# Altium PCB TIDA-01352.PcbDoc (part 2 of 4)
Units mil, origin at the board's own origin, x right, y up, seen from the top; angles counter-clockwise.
Board outline 6496.06 x 8661.42 mil, 4 copper layers (Top Layer, GND, PWR, Bottom Layer), stack 79.834 mil thick; 456 components, 240 nets, 1197 pads, 446 vias.
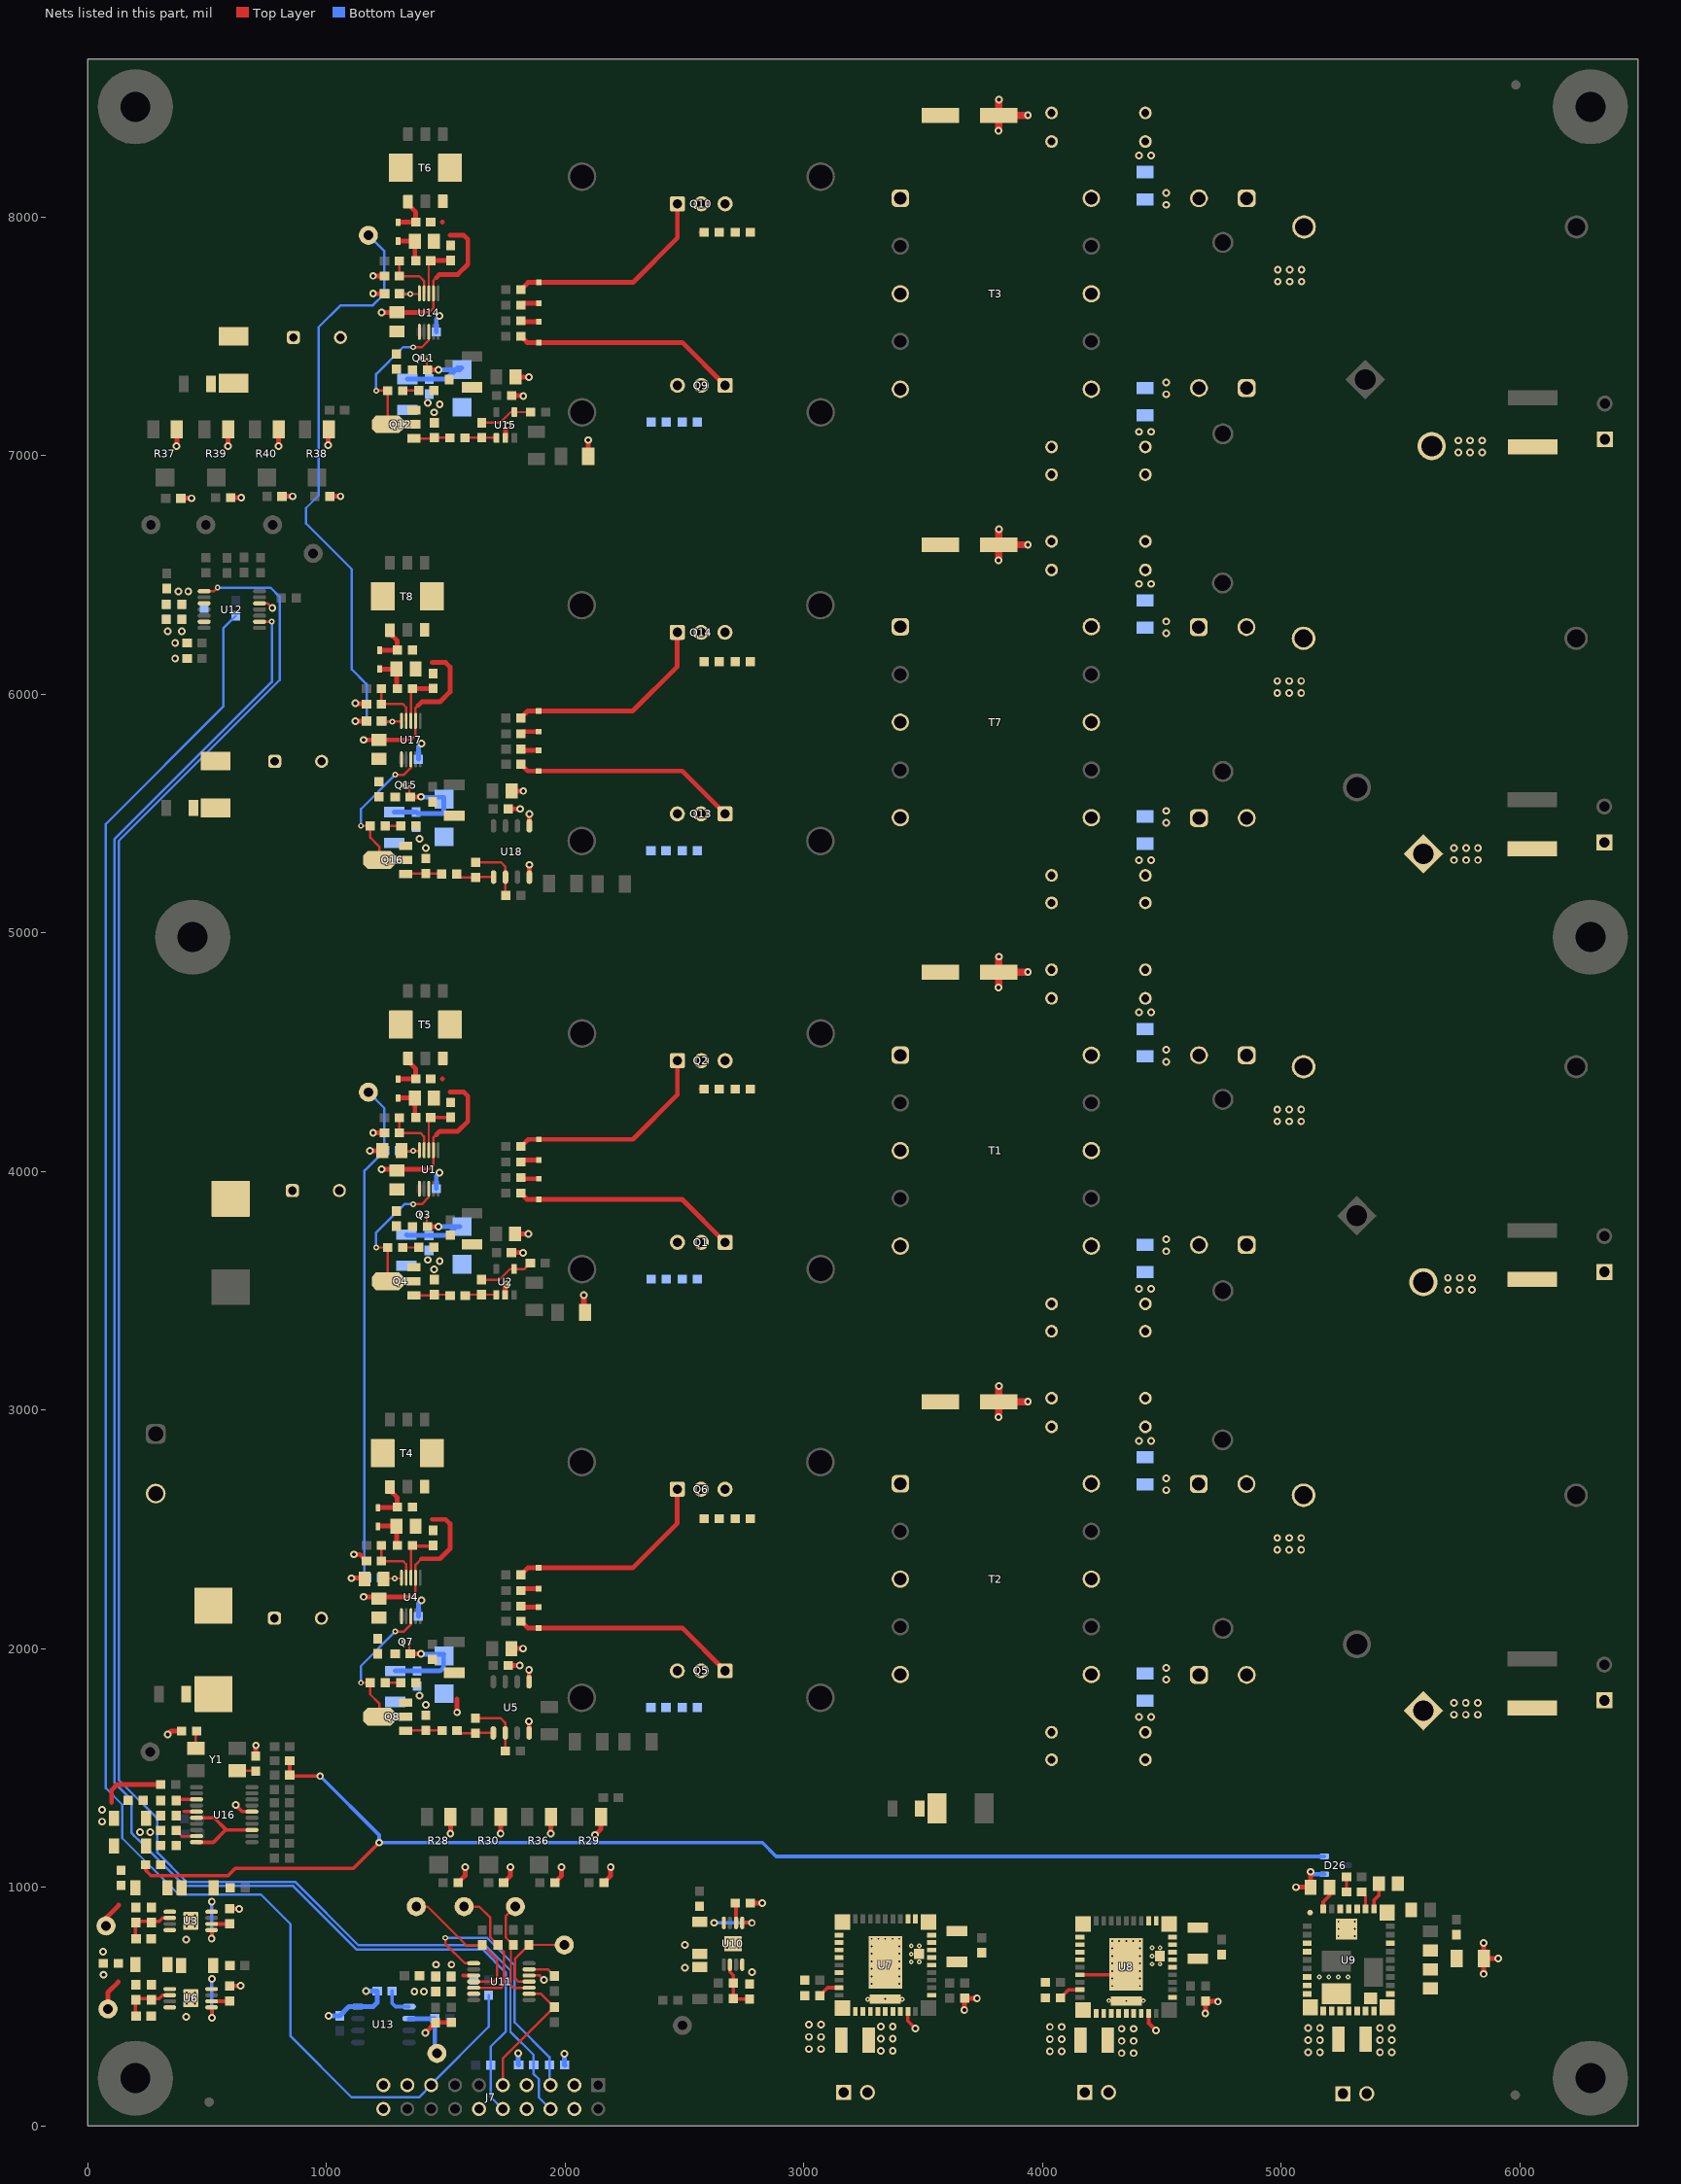
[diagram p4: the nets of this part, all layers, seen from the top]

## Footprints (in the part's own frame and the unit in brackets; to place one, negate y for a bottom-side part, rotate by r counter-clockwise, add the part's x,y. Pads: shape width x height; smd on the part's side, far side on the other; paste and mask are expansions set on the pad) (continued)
Nichicon_2000x3000_Snap [mm]
  rrect3% 3x3 hole 2.2: 1(-5,0)
  round 3 hole 2.2: 2(5,0)
  silkscreen extent -10.6,-10.6 10.6,10.6
"NY PMS 440 0025 PH" [mm] "4-40 nylon screw and mounting hole"
  round 8 hole 3.2: 1(0,0)
On-Shore_OSTT7020150 [mm] "Terminal Block, 6.35mm, 2x1, TH"
  rrect50% 2.1x2.1 hole 1.6: 1(-3.175,0)
  round 2.1 hole 1.6: 2(3.175,0)
  silkscreen extent -6.98,-8 6.35,5
PhoenixConact_1727010 [mm]
  rect 1.7x1.7 hole 1.1: 1(-1.905,0)
  round 1.7 hole 1.1: 2(1.905,0)
  silkscreen extent -3.81,-3.6 3.81,3.6
PR01 [mm] "TH, 2-Leads, Axial, Dia 2.5mm, Pin Spacing 9.98mm"
  round 1.35 hole 0.85: 1(-4.99,0) 2(4.99,0)
  silkscreen extent -3.25,-1.25 3.25,1.25
PW0014A_N [mm] "TSOP, 14-Leads, Body 5x4.4mm, Pitch 0.65mm, IPC Medium Density"
  oval 1.4x0.45 smd: 1(-2.95,1.95) 2(-2.95,1.3) 3(-2.95,0.65) 4(-2.95,0) 5(-2.95,-0.65) 6(-2.95,-1.3) 7(-2.95,-1.95) 8(2.95,-1.95) 9(2.95,-1.3) 10(2.95,-0.65) 11(2.95,0) 12(2.95,0.65) 13(2.95,1.3) 14(2.95,1.95)
  silkscreen extent -3.4,-2.55 1.85,2.55
PW0020A_N [mm] "TSOP, 20-Leads, Body 6.5x4.4mm, Pitch 0.65mm, IPC Medium Density"
  oval 1.4x0.45 smd: 1(-2.95,2.925) 2(-2.95,2.275) 3(-2.95,1.625) 4(-2.95,0.975) 5(-2.95,0.325) 6(-2.95,-0.325) 7(-2.95,-0.975) 8(-2.95,-1.625) 9(-2.95,-2.275) 10(-2.95,-2.925) 11(2.95,-2.925) 12(2.95,-2.275) 13(2.95,-1.625) 14(2.95,-0.975) 15(2.95,-0.325) 16(2.95,0.325) 17(2.95,0.975) 18(2.95,1.625) 19(2.95,2.275) 20(2.95,2.925)
  silkscreen extent -3.5,-3.3 1.85,3.4
RKG0041A [mm] "QFN-41, 9X11mm"
  round 0.6 smd: 1(-4.1,5.05)
  rect 0.95x0.6 smd paste-0.025: 2(-4.425,3.6) 3(-4.425,2.7) 4(-4.425,1.8) 5(-4.425,0.9) 6(-4.425,0) 7(-4.425,-0.9) 8(-4.425,-1.8) 9(-4.425,-2.7) 10(-4.425,-3.6) 20(4.425,-3.6) 21(4.425,-2.7) 22(4.425,-1.8) 23(4.425,-0.9) 24(4.425,0) 25(4.425,0.9) 26(4.425,1.8) 27(4.425,2.7) 28(4.425,3.6)
  rect 1.6x1.7 smd paste-0.8: 11(-4.1,-5.05) 19(4.1,-5.05) 29(4.1,5.05)
  rect 0.6x0.95 smd paste-0.025: 12(-2.7,-5.425) 13(-1.8,-5.425) 14(-0.9,-5.425) 15(0,-5.425) 16(0.9,-5.425) 17(1.8,-5.425) 18(2.7,-5.425) 30(2.7,5.425) 31(1.8,5.425) 32(0.9,5.425) 33(0,5.425) 34(-0.9,5.425) 35(-1.8,5.425) 36(-2.7,5.425)
  rect 2.3x2.25 smd paste-1.2 mask+0: 37(-0.22,3.3)
  rect 3.1x2.2 smd paste-1.1: 38(-1.3,-0.11) 39(-1.3,-3.59)
  rect 1.4x1.24 smd paste-0.7: 40(2.33,-4.06)
  rect 2.04x3.05 smd paste-1.02: 41(2.65,-1.32)
  silkscreen extent -5.13,-6.11 5.12,6.12
RVQ0043A [mm]
  rect 1.65x1.65 smd paste-0.225: 1(-4.575,4.575) 11(-4.575,-4.575) 21(4.575,-4.575) 31(4.575,4.575)
  rect 0.95x0.5 smd paste-0.025: 2(-4.925,3.2) 3(-4.925,2.4) 4(-4.925,1.6) 5(-4.925,0.8) 6(-4.925,0) 7(-4.925,-0.8) 8(-4.925,-1.6) 9(-4.925,-2.4) 10(-4.925,-3.2) 22(4.925,-3.2) 23(4.925,-2.4) 24(4.925,-1.6) 25(4.925,-0.8) 26(4.925,0) 27(4.925,0.8) 28(4.925,1.6) 29(4.925,2.4) 30(4.925,3.2)
  rect 0.5x0.95 smd paste-0.025: 12(-3.2,-4.925) 13(-2.4,-4.925) 14(-1.6,-4.925) 15(-0.8,-4.925) 16(0,-4.925) 17(0.8,-4.925) 18(1.6,-4.925) 19(2.4,-4.925) 20(3.2,-4.925) 32(3.2,4.925) 33(2.4,4.925) 34(1.6,4.925) 35(0.8,4.925) 36(0,4.925) 37(-0.8,4.925) 38(-1.6,4.925) 39(-2.4,4.925) 40(-3.2,4.925)
  rect 3.55x5.6 smd paste-1.78 mask+0: 41(0,0.3)
  rect 1.05x1.12 smd paste-1: 42(3.575,1.187)
  rect 3.3x1 smd paste-0.5 mask+0: 43(0,-3.6)
  Top Layer region: 1.6,-4.1 2.25,-4.1 2.25,-3.1 1.6,-3.1
  Top Layer region: -2.25,-4.1 -1.6,-4.1 -1.6,-3.1 -2.25,-3.1
  Top Layer region: 2.925,0.027 4.1,0.027 4.1,0.762 2.925,0.762
  Top Layer region: 2.45,0.027 3.08,0.027 3.08,1.812 2.45,1.812
  Top Layer region: 2.45,1.712 4.1,1.712 4.1,2.347 2.45,2.347
  silkscreen extent -5.65,-5.65 5.65,5.65
SM_RADIAL_E [mm] "8 x 6.2mm:  Panasonic E"
  rect 4x1.6 smd: 1(-3.1,0) 2(3.1,0)
  silkscreen extent -4.25,-4.25 4.25,4.25
SMA [mm] "Molded Diode, 2-Leads, Body 4.3x2.6mm, IPC Medium Density, based on OnSemi component dimensions and land pattern"
  rect 2x2 smd: 1(-2,0) 2(2,0)
  silkscreen extent -3.66,-1.57 2.79,1.57
SOD-323F [mm] "NXP recommended land pattern"
  rect 0.6x0.6 smd paste-0.05: 1(-1.1,0) 2(1.1,0)
  silkscreen extent -2.06,-0.86 1.53,0.86
SOT-23 [mm] "SOT23, 3-Leads, Body 2.9x1.3mm, Pitch 0.95mm, Lead Span 2.5mm, IPC Medium Density"
  rrect50% 1x0.6 smd: 1(-1.2,0.95) 2(-1.2,-0.95) 3(1.2,0)
  silkscreen extent -1.62,-1.5 0.7,1.5
SOT-89-3 [mm] "SOT, 3-Leads, Body 4.6 x 2.6 mm, Pitch 1.5mm"
  rect 1.4x0.9 smd: 1(-1.9,1.5) 3(-1.9,-1.5)
  rect 1.8x0.9 smd: 2(-1.7,0)
  oct 3.4x1.9 smd: 4(0.9,0)
  silkscreen extent -1.3,-2.45 1.33,2.45
Sullins_xxxC010DAAN [mm] "Header, 2.54mm, 10x2, TH"
  rect 1.5x1.5 hole 1: 1(-1.27,11.43)
  round 1.5 hole 1: 2(1.27,11.43) 3(-1.27,8.89) 4(1.27,8.89) 5(-1.27,6.35) 6(1.27,6.35) 7(-1.27,3.81) 8(1.27,3.81) 9(-1.27,1.27) 10(1.27,1.27) 11(-1.27,-1.27) 12(1.27,-1.27) 13(-1.27,-3.81) 14(1.27,-3.81) 15(-1.27,-6.35) 16(1.27,-6.35) 17(-1.27,-8.89) 18(1.27,-8.89) 19(-1.27,-11.43) 20(1.27,-11.43)
  silkscreen extent -2.5,-12.7 2.5,13.14
TEC_282834-2 [mm] "TEC"
  rect 1.6x1.6 hole 1.1: 1(-1.27,0)
  round 1.6 hole 1.1: 2(1.27,0)
  silkscreen extent -3.66,-3.4 2.9,3.4
TO-220AC [mm]
  rrect50% 1.9x1.9 hole 1.4: 1(-2.54,0)
  round 1.9 hole 1.4: 3(2.54,0)
  silkscreen extent -5.25,-1.64 5.26,3.01
TRIM_3224X [mm] "Bourns"
  rect 1.9x1.3 smd: 1(-2.55,1.25) 3(-2.55,-1.25)
  rect 1.9x2 smd: 2(2.55,0)
  silkscreen extent -1.9,-2.5 1.9,2.5
WCAP-ATLI_1300x3000 [mm] "TH, 2-Leads, Dia 13mm, Pin Spacing 5mm"
  rrect50% 1.4x1.4 hole 0.9: 1(-2.5,0)
  round 1.4 hole 0.9: 2(2.5,0)
  silkscreen extent -6.75,-6.75 6.75,6.75
Wurth_750340744 [mm] "SMD, 8-Leads, Body 6.13x7.37mm"
  rrect10% 1.45x1.02 smd: 1(-3.6,1.85) 2(-3.575,0) 3(-3.575,-1.85) 4(3.575,-1.85) 5(3.575,0) 6(3.575,1.85)
  rrect4% 3x2.54 smd: 7(0,-2.62) 8(0,2.62)
  silkscreen extent -3.4,-3.69 3.07,3.69
Wurth_750343473 [mm] "TH, 10-Leads, Body 29.21x27.94mm"
  rrect50% 1.85x1.85 hole 1.32: 1(-10.16,10.16)
  round 1.85 hole 1.32: 2(-10.16,5.08) 3(-10.16,0) 4(-10.16,-5.08) 5(-10.16,-10.16) 6(10.16,-10.16) 7(10.16,-5.08) 8(10.16,0) 9(10.16,5.08) 10(10.16,10.16)
  silkscreen extent -14.74,-14.12 14.74,14.12
YJC0003A [mm] "TI"
  rrect50% 0.25x0.2 on Top Paste: 0(-0.325,0.2) 0(-0.325,-0.2)
  rrect80% 0.35x0.25 smd paste-0.13 mask+0: 1(-0.325,0.175) 2(-0.325,-0.175)
  rrect57% 0.35x0.6 smd paste-0.05 mask+0: 3(0.325,0)

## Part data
/SD1 /SD2 CLK_1V8 CLK_3V3 SYNC VCON-A1 VCON-A2 VCON-B1 VCON-B2 VCON-C1 VCON-C2 VCON-D1 VCON-D2 VDD_5V3 VREF_5V: "Test Point, Miniature, White, TH"
C1 C7 C10 C28 C31 C103: "CAP, CERM, 0.01 µF, 50 V, +/- 10%, X7R, 0603"
C2 C3 C66 C79: "CAP, AL, 470 µF, 63 V, +/- 20%, TH"
C4 C5 C18 C19 C21 C22: "CAP, CERM, 47 µF, 16 V, +/- 10%, X5R, 1210"
C6 C23: "CAP, CERM, 10 µF, 50 V, +/- 10%, X5R, 1210"
C8 C9 C11 C29 C30 C101 C102 C104: "CAP, CERM, 10 µF, 50 V, +/- 10%, X5R, 1206"
C12 C25 C33 C34 C35 C37 C41 C105: "CAP, CERM, 1 µF, 25 V, +/- 10%, X5R, 0603"
C13 C26 C38 C52 C53 C64 C65 C77 C78 C90 C91 C106 C109 C110 C111 C112 C117 C122 C127 C132: "CAP, CERM, 0.1 µF, 50 V, +/- 10%, X7R, 0603"
C14 C15 C16 C92 C93 C94 C95 C96: "CAP, CERM, 0.1 µF, 25 V, +/- 5%, X7R, 0603"
C17: "CAP, CERM, 2.2 µF, 50 V, +/- 10%, X5R, 0805"
C20: "CAP, CERM, 4.7 µF, 50 V, +/- 10%, X5R, 1206"
C24 C32 C36 C40: "CAP, CERM, 10 µF, 25 V, +/- 20%, X5R, 0603"
C27 C39: "CAP, CERM, 100 pF, 50 V, +/- 5%, C0G/NP0, 0603"
C42 C54 C67 C80: "CAP, AL, 100 µF, 400 V, +/- 20%, TH"
C43 C44 C45 C55 C56 C57 C68 C69 C70 C81 C82 C83: "CAP, CERM, 1000 pF, 25 V, +/- 10%, X7R, 0603"
C46 C58 C71 C84 C116 C121 C126 C131: "CAP, CERM, 22 µF, 25 V, +/- 20%, X5R, 1210"
C47 C51 C59 C63 C72 C76 C85 C89: "CAP, CERM, 1 µF, 50 V, +/- 10%, X7R, 0805"
C48 C60 C73 C86: "CAP, CERM, 100 pF, 50 V, +/- 1%, C0G/NP0, 0603"
C49 C61: "CAP, CERM, 15 µF, 35 V, +/- 20%, X5R, 0805"
C50 C62 C75 C88: "CAP, CERM, 1 µF, 35 V, +/- 10%, X5R, 0603"
C74 C87: "CAP, CERM, 6.8 µF, 25 V, +/- 10%, X5R, 0603"
C97 C98 C99 C100: "CAP, AL, 22 µF, 50 V, +/- 20%, 0.7 ohm, SMD"
C107 C108: "CAP, CERM, 10 pF, 50 V, +/- 1%, C0G/NP0, 0603"
C113 C115 C118 C120 C123 C125 C128 C130: "CAP, CERM, 470 pF, 500 V, +/- 10%, X7R, 1206"
C114 C119 C124 C129: "CAP, CERM, 1 µF, 250 V, +/- 10%, X7R, 2220"
C133: "CAP, CERM, 470 pF, 50 V, +/- 5%, C0G/NP0, 0603"
D2 D3 D5 D10 D14 D16 D20 D22: "Diode, Schottky, 600 V, 10 A, TH"
D4 D9 D15 D21: "Diode, Switching, 75 V, 0.3 A, SOD-523F"
D6 D11 D17 D23: "Diode, Zener, 11 V, 1.5 W, SMA"
D7 D8 D12 D13 D18 D19 D24 D25: "Diode, Schottky, 10 V, 3 A, SOD-323F"
D26: "Diode, Switching, 100 V, 0.215 A, SOT-23"
ESD-LOGO: library part ESD_Susceptible, "ESD Susceptible Symbol"
F1 F2: "Fuse, 15 A, 250 VAC, 72 VDC, SMD"
F3 F4 F5: library part "SSQ 8", "FUSE BRD MNT 10A 125VAC/VDC"
FID1 FID2 FID3 FID4 FID5 FID6: "Fiducial mark.  There is nothing to buy or mount."
H1 H2 H3 H4 H5 H6: "Machine Screw, Round, #4-40 x 1/4, Nylon, Philips panhead"
H5 H6 H13 H14 H17 H18 H21 H22: "HEATSINK TO-220 .500\" COMPACT"
H7 H12 H15 H16 H19 H20 H23 H24: "HEATSINK, ALUM, ANOD, for TO-220"
H8 H9 H10 H11 H12 H13: "Standoff, Hex, 1\"L #4-40 Nylon"
J1: "Terminal Block, 6.35mm, 2x1, TH"
J2 J3 J8 J9: "Conn Term Block, 2POS, 3.81mm, TH"
J4 J5 J6: "Terminal Block, 2x1, 2.54mm, TH"
J7: "Header, 2.54mm, 10x2, Gold, TH"
L1 L9: "Ferrite Bead, 600 ohm @ 100 MHz, 0.5 A, 0603"
L2 L3 L6 L7: "Inductor, Wirewound, 470 µH, 4 A, 0.125 ohm, TH"
L5 L8: "Ferrite Bead, 5 ohm @ 100 MHz, 0.7 A, 0603"
LBL1: library part THT-14-423-10, "Thermal Transfer Printable Labels, 0.650\" W x 0.200\" H - 10,000 per roll"
Logo9: library part EURoHS_Exempt
Logo10: library part FCC_disclaimer, "FCC_disclaimer"
LOGO11 LOGO12: library part IEC_HighVoltage, "IEC 61010-1 High Voltage Warning"
Logo13 Logo14 Logo15 Logo16: library part IEC_Caution, "IEC 61010-1 Caution Warning"
Q1 Q2 Q5 Q6 Q9 Q10 Q13 Q14: "MOSFET, N-CH, 80 V, 100 A, KCS0003B (TO-220-3)"
Q3 Q7 Q11 Q15: "MOSFET, N-CH, 30 V, 3.1 A, YJC0003A (PICOSTAR-3)"
Q4 Q8 Q12 Q16: library part "FCX493TA, Diodes Inc.", "Transistor, NPN, 100 V, 1 A, SOT-89"
R1 R5 R6 R9 R10 R11 R13 R18 R19 R21 R22 R23 R24 R25 R27 R31 R32 R33 R34 R35 R45 R46 R47 R48 R51 R53 R54 R64 R65 R66 R67 R70 R72 R73 R85 R86 R87 R88 R91 R93 R94 R106 R107 R108 R109 R112 R114 R115 R122 R123 R124 R125 R126 R127 R128 R131 R132 R133 R134 R135 R136 R137 R138 R139 R142 R143 R148 R149 R150 R151 R168 R169: "RES, 0, 5%, 0.1 W, 0603"
R2 R41 R42 R58 R61 R78 R81 R82 R98 R102 R103 R120: "RES, 10.0 k, 1%, 0.1 W, 0603"
R3 R4 R80 R101: "RES, 0, 1%, 0.5 W, 1206"
R7 R14: "RES, 200 k, 1%, 0.1 W, 0603"
R8: "RES, 8.87 k, 1%, 0.1 W, 0603"
R12 R55 R75 R95 R117: "RES, 1.00 k, 1%, 0.1 W, 0603"
R15: "RES, 52.3 k, 1%, 0.125 W, 0805"
R16: "RES, 93.1 k, 1%, 0.125 W, 0805"
R17: "RES, 5.11 k, 1%, 0.1 W, 0603"
R20: "RES, 348 k, 1%, 0.1 W, 0603"
R26 R130 R141: "RES, 100 k, 1%, 0.1 W, 0603"
R28 R29 R30 R36 R37 R38 R39 R40: "Trimmer, 1 K, 0.25 W, SMD"
R43 R62: "RES, 4.02, 1%, 0.125 W, 0805"
R44 R63 R84 R105: "RES, 300, 1%, 0.1 W, 0603"
R49 R50 R68 R69 R89 R90 R110 R111: "RES, 10.0, 1%, 0.1 W, 0603"
R52 R71 R92 R113: "RES, 26.7 k, 1%, 0.1 W, 0603"
R56 R74: "RES, 300 k, 1%, 0.25 W, 1206"
R57 R60 R76 R79 R97 R100 R118 R121: "RES, 47.0 k, 1%, 0.1 W, 0603"
R59 R77 R99 R119 R170: "RES, 10.0 k, 1%, 0.25 W, 1206"
R83 R104: "RES, 4.99, 1%, 0.125 W, 0805"
R96: "RES, 110 k, 1%, 0.25 W, 1206"
R116: "RES, 100 k, 1%, 0.25 W, 1206"
R129: "RES, 51.7 k, 0.5%, 0.1 W, 0603"
R140: "RES, 178 k, 1%, 0.1 W, 0603"
R144 R145: "RES, 10 k, 5%, 0.1 W, 0603"
R146: "RES, 174 k, 1%, 0.125 W, 0805"
R147: "RES, 63.4 k, 1%, 0.125 W, 0805"
R152 R153 R154 R155 R156 R157 R158 R159 R160 R161 R162 R163 R164 R165 R166 R167: "RES, 1.1 k, 5%, 1 W, AEC-Q200 Grade 0, D2.5xL6.5mm"
T1 T2 T3 T7: "Transformer, 100 uH, TH"
T4 T5 T6 T8: "Transformer, TH"
U1 U4 U14 U17: "100V Push-Pull Current Mode PWM Controller, 10-pin MSOP, Pb-Free"
U2 U15: "36-V, Single-Supply, Low-Power Operational Amplifiers for Cost-Sensitive Systems, DBV0005A (SOT-5)"
U3 U6 U10: "Single Output High PSRR LDO, 150 mA, Adjustable 1.2 to 33 V Output, 3 to 36 V Input, with Ultra-Low Noise, 8-pin MSOP (DGN), -40 to 125 degC, Green (RoHS & no Sb/Br)"
U5 U18: "36-V, Single-Supply, Low-Power Operational Amplifier for Cost-Sensitive Systems, D0008A (SOIC-8)"
U7 U8: "SIMPLE SWITCHER 4.5-V to 42-V Input, 2-A Power Module, RVQ00043A (B3QFN-43)"
U9: "4.5-V to 40-V Input, 15-W, Negative Output, Integrated Power Solution, RKG0041A (B1QFN-41)"
U11 U12: "QUAD 12-BIT, 1LSB INL, BUFFERED, VOLTAGE-OUTPUT DIGITAL-to-ANALOG CONVERTERS, PW0014A (TSSOP-14)"
U13: "Low Noise, Very Low Drift, Precision Voltage Reference, -40 to 125 degC, 8-pin SOIC (D), Green (RoHS & no Sb/Br)"
U16: "Programmable 3-PLL VCXO Clock Synthesizer With 1.8-V, 2.5-V and 3.3-V LVCMOS Outputs, PW0020A (TSSOP-20)"
Y1: "Crystal, 8 MHz, 18 pF, SMD"
ZZ8: library part AssemblyNoteLabel
ZZ9 ZZ10 ZZ11: library part AssemblyNote

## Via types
v1: diameter 32, hole 16, Top Layer to Bottom Layer, tented both sides, 325 vias
v2: diameter 19.68, hole 7.87, Top Layer to Bottom Layer, 75 vias
v3: diameter 24, hole 12, Top Layer to Bottom Layer, tented both sides, 46 vias

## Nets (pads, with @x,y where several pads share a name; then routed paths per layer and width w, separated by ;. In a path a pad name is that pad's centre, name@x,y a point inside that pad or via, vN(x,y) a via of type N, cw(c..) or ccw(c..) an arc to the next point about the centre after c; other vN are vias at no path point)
/CLR1: J7.9 R124.1 U11.9 | length 553.9
  Top Layer w10: J7.9@1739.26,170.63 1739.26,281.63 R124.1@1955.08,497.45 ; U11.9@1849.48,553.45 1899.08,553.45 R124.1@1955.08,497.45 ; R124.1@1955.36,497.73 R124.1@1955.08,497.45
  Bottom Layer w10: J7.9@1735.53,174.39 J7.9@1744.01,174.39
/CLR2: J7.10 R125.2 U12.9 | length 7859.4
  Top Layer w10: U12.9@720.24,6303.53 v3(771.43,6303.53)
  Bottom Layer w10: v3(771.43,6303.53) 771.43,6051.43 112,5392 112,1438 183,1367 183,1228.54 190.89,1220.65 190.89,1219.48 207.88,1202.5 209.05,1202.5 406.54,1005 861,1005 1126.37,739.63 1654.71,739.63 1751.26,643.09 1751.26,394.63 1688.75,332.13 R125.2@1688.75,254.63 1688.75,121.14 J7.10@1739.26,70.63
/LDAC1: J7.5 R122.1 U11.1 | length 1078.6
  Top Layer w10: v3(1499,788) 1499,763 1580.59,681.41 U11.1@1617.19,681.41
  Bottom Layer w10: v3(1499,788) 1672.89,788 1789.26,671.63 1789.26,433.63 1934.76,288.13 R122.1@1934.76,255.63 1934.76,175.13 J7.5@1939.26,170.63
/LDAC2: J7.6 R123.2 U12.1 | length 8282.2
  Top Layer w10: U12.1@487.96,6431.48 529.38,6431.48 v3(544.1,6446.2)
  Bottom Layer w10: v3@543.79,6445.89 v3(544.1,6446.2) 766.1,6446.2 804.1,6408.2 804.1,6058.65 130,5384.54 130,1450 292,1288 292,1145 414,1023 869,1023 1134.37,757.63 1665.26,757.63 1771.26,651.63 1771.26,394.63 1868.75,297.14 R123.2@1868.75,255.63 1868.75,217.14 1890.26,195.63 1890.26,119.63 J7.6@1939.26,70.63
/SD1: /SD1.1 R54.1 R73.1 | length 2101.1
  Bottom Layer w10: R54.1@1168.5,2297 1160,2305.5 1160,4003.5 R73.1@1243.5,4087 1243.5,4264.5 /SD1.1@1176,4332
/SD2: /SD2.1 R94.1 R115.1 | length 2383.4
  Bottom Layer w10: R94.1@1168.5,5888.01 1168.5,6041.8 1106.1,6104.2 1106.1,6523.9 915,6715 915,6779.54 968,6832.54 968,7538 1059.75,7629.75 1195.25,7629.75 R115.1@1243.5,7678.01 1243.5,7855.5 /SD2.1@1176,7923.01
/SYNC: J7.15 R148.2 R149.2 | length 7893.4
  Bottom Layer w10: R149.2@620,6328.5 569.1,6277.61 569.1,5949.1 76,5456 76,1415.19 145,1346.19 145,1205.54 381.54,969 726,969 850,845 850,375.89 1106.26,119.63 1388.26,119.63 J7.15@1439.26,170.63 1439.26,174.63 1680,415.38 R148.2@1680,547.5
A_VOUT: C17.1 C21.1 C22.1 J6.2 R16.2 R147.1 U9.1 U9.4 U9.5 U9.8 U9.9 U9.16 U9.17 U9.18 U9.19 U9.20 U9.29 U9.32 U9.33 U9.34 U9.37 U9.40
  other v1: 5414.02,308 5464.02,308 5414.02,359 5464.02,359 5414.02,410 5464.02,410
  other v2: 5160.11,624 5200.11,624 5240.11,624 5280.11,624 5240.59,794.21 5308.31,794.21 5240.59,824.92 5308.31,824.92 5240.59,855.63 5308.31,855.63
CLK_1.8V: C11.1 L9.1 R128.1 R138.1 | length 270.7
  Top Layer w20: 100,1355 100,1407.72 122.78,1430.5 R138.1@306.39,1430.5
  Bottom Layer w30: v1@65,634.58 v1(66.53,633.06)
  other v1: 65,730 60,1275 60,1325
CLK_3.3V: C104.1 D26.2 L1.1 R139.1 R144.1 R145.1 | length 5623.1
  Top Layer w15: L1.1@242.39,1094.5 242.39,1071.61 265,1049 588,1049 618,1079 1113,1079 v1(1221,1187) ; R144.1@846.5,1530 R145.1@846.5,1470 850.5,1466 v1(974,1466)
  Bottom Layer w15: v1(974,1466) 1221,1219 v1(1221,1187) 2827,1187 2884.6,1129.4 D26.2@5181.76,1129.4
CS_N1: C43.1 R44.1 U4.8 | length 212.7
  Top Layer w10: U4.8@1354.13,2297.13 1354.13,2426.2 R44.1@1360.35,2432.43
  Top Layer w15: R44.1@1360.35,2429.8 C43.1@1435.19,2429.8
CS_N2: C68.1 R84.1 U17.8 | length 224.6
  Top Layer w10: U17.8@1354.13,5888.14 1354.13,6017.21 R84.1@1360.35,6023.43
  Top Layer w20: R84.1@1360.35,6023.43 1446.92,6023.43 C68.1@1447,6023.51
CS_P1: C55.1 R63.1 U1.8 | length 224.3
  Top Layer w10: U1.8@1429.13,4088.71 1429.13,4217.31 R63.1@1437.5,4225.68 ; C55.1@1520.04,4225.68 C55.1@1521,4226.64
  Top Layer w15: R63.1@1437.5,4225.68 C55.1@1520.04,4225.68
CS_P2: C81.1 R105.1 U14.8 | length 224.3
  Top Layer w10: U14.8@1429.13,7679.72 1429.13,7808.32 R105.1@1437.5,7816.69
  Top Layer w20: R105.1@1437.5,7816.69 1520.04,7816.69 C81.1@1521,7817.65
GND: C2.2 C3.2 C4.2 C5.2 C6.2 C8.2 C9.2 C10.1 C11.2 C12.2 C13.2 C14.2 C15.2 C16.2 C18.2 C19.2 C20.2 C21.2 C22.2 C23.2 C24.2 C25.2 C26.2 C27.2 C29.2 C30.2 C31.1 C32.2 C33.2 C34.2 C35.2 C36.2 C37.2 C38.2 C39.2 C40.2 C41.2 C42.1 C43.2 C46.2 C47.2 C49.2 C50.2 C51.2 C52.2 C54.2 C55.2 C58.2 C59.2 C61.2 C62.2 C63.2 C64.2 C66.2 C67.1 C68.2 C71.2 C72.2 C74.2 C75.2 C76.2 C77.2 C79.2 C80.2 C81.2 C84.2 C85.2 C87.2 C88.2 C89.2 C90.2 C92.2 C93.2 C94.2 C95.2 C96.2 C97.2 C98.2 C99.2 C100.2 C101.2 C102.2 C103.1 C104.2 C105.2 C106.2 C107.1 C108.1 C109.2 C110.2 C111.2 C112.2 C114.2 C116.2 C117.2 C119.2 C121.2 C122.2 C124.2 C126.2 C127.2 C129.2 C131.2 C132.2 D6.2 D11.2 D17.2 D23.2 D26.1 J1.2 J2.1 J3.1 J4.1 J5.1 J6.1 J7.3 J7.4 J7.7 J7.8 J7.12 J7.17 J7.19 J7.20 J8.1 J9.1 Q1.3 Q2.3 Q4.3 Q5.3 Q6.3 Q8.3 Q9.3 Q10.3 Q12.3 Q13.3 Q14.3 Q16.3 R2.1 R6.1 R7.1 R8.1 R13.1 R14.1 R15.1 R17.1 R26.2 R28.1 R29.1 R30.1 R36.1 R37.1 R38.1 R39.1 R40.1 R41.1 R43.2 R46.2 R47.2 R52.1 R53.1 R58.1 R62.2 R65.2 R66.2 R71.1 R72.1 R77.1 R78.1 R81.1 R83.2 R86.2 R87.2 R92.1 R93.1 R98.1 R102.1 R104.2 R107.2 R108.2 R113.1 R114.1 R119.1 R120.1 R122.2 R123.1 R130.2 R141.2 R152.2 R153.2 R154.1 R155.1 R156.2 R157.2 R158.1 R159.1 R160.2 R161.2 R162.1 R163.1 R164.2 R165.2 R166.1 R167.1 T1.8 T2.8 T3.8 T4.3 T5.3 T6.3 T7.8 T8.3 U1.7 U2.2 U3.4 U3.9 U4.7 U5.4 U5.5 U6.4 U6.9 U7.1 U7.2 U7.3 U7.4 U7.5 U7.11 U7.12 U7.19 U7.29 U7.30 U7.31 U7.32 U7.33 U7.41 U8.1 U8.2 U8.3 U8.4 U8.5 U8.7 U8.11 U8.12 U8.19 U8.29 U8.30 U8.31 U8.32 U8.33 U8.41 U9.10 U9.11 U9.12 U9.13 U9.14 U9.15 U9.39 U10.4 U10.9 U11.6 U11.12 U12.6 U12.12 U13.4 U14.7 U15.2 U16.5 U16.9 U16.16 U17.7 U18.4 U18.5 | length 8649.8
  Top Layer w10: C106.2@370.89,1238.35 394.75,1214.5 U16.9@455.89,1214.5 ; U12.12@720.24,6380.3 755.01,6380.3 v1(774.1,6361.2) ; 1333,2217.43 1355,2217.43 1373.81,2236.24 U4.7@1373.81,2297.13 1373.81,2351.24 1399,2376.43 ; 1333,5808.43 1355,5808.43 1373.81,5827.24 U17.7@1373.81,5888.14 1373.81,5942.24 1384.57,5953 1385,5953 ; 1408,4009 1430,4009 1448.81,4027.81 U1.7@1448.81,4088.71 1448.81,4142.81 1460,4154 1461,4154 ; 1408,7600.01 1430,7600.01 1448.81,7618.82 U14.7@1448.81,7679.72 1448.81,7733.82 1461.99,7747 ; U11.12@1849.48,630.22 1893.78,630.22 v1(1912.37,611.63)
  Top Layer w15: 403.25,1316.86 U16.5@455.89,1316.86 ; v1(620.89,1344.5) 620.89,1343.5 647.53,1316.86 U16.16@688.17,1316.86 ; U7.19@3436.6,479.83 3436.6,439.24 v1(3467.11,408.73) ; U8.7@4157.21,633.5 4307.8,633.5 U8.41@4351.11,676.81 ; U8.19@4445.6,471.1 4445.6,430.51 v1(4476.11,400)
  Top Layer w20: v1(335,1640.6) 348.9,1654.5 C108.1@393.39,1654.5 ; v1(372.63,7038.9) 373.42,7039.68 R37.1@373.42,7109.29 ; C15.2@390.39,6820.8 v1(435.39,6820.8) ; v1(587.63,7038.9) 588.42,7039.68 R39.1@588.42,7109.29 ; C10.1@595.37,586.19 v1@641.92,586.19 ; C103.1@595.37,910.06 634.21,910.06 v1(635.37,908.9) ; C95.2@598.69,6823.9 v1(643.69,6823.9) ; C107.1@704.5,1549.61 704.5,1594.1 v1(705,1594.61) ; v1(799.24,7038.9) 800.03,7039.68 R40.1@800.03,7109.29 ; C94.2@814.31,6828.9 v1(859.31,6828.9) ; v1(1006.84,7043.5) 1007.63,7044.29 R38.1@1007.63,7113.9 ; C96.2@1014.31,6828.9 v1(1059.31,6828.9) ; v1(1105,2295) 1105.43,2295.43 C49.2@1168.5,2295.43 ; v1(1115,2395) 1140.2,2395 R52.1@1165.64,2369.57 ; v1(1121,5887.29) 1121.86,5886.43 C74.2@1168.5,5886.43 ; v1(1121,5961.43) 1121.86,5960.57 R92.1@1168.5,5960.57 ; v1(1156,2217.43) 1333,2217.43 ; v1(1156,5808.43) C72.2@1220.13,5808.43 1333,5808.43 ; R52.1@1168.08,2367.13 R52.1@1165.64,2369.57 ; R52.1@1168.5,2369.57 R52.1@1165.64,2369.57 ; v1(1183,4087) C61.2@1235,4087 C61.2@1243.5,4087 ; v1(1196,4162) 1196.86,4161.14 R71.1@1243.5,4161.14 ; v1(1196,7678.87) 1196.86,7678.01 C87.2@1243.5,7678.01 ; v1(1196,7753.01) 1196.86,7752.15 R113.1@1243.5,7752.15 ; v1(1231,4009) 1408,4009 ; v1(1231,7600.01) C85.2@1295.13,7600.01 1408,7600.01 ; 1385,5953 1399.43,5967.43 1476,5967.43 1518,6009.43 1518,6114.43 1500,6132.43 1444,6132.43 ; 1399,2376.43 1476,2376.43 1518,2418.43 1518,2523.43 1500,2541.43 1444,2541.43 ; v1(1414.37,389.29) C32.2@1457.6,432.52 1458.6,433.52 C33.2@1523.6,433.52 ; v1(1417.26,1764.2) v1@1417.46,1764.01 ; v1(1417.26,5355.21) v1@1417.46,5355.02 ; v1(1452,3590) v1@1452.2,3589.8 ; v1(1452,7181.01) v1@1452.2,7180.81 ; 1461,4154 1475,4168 1551,4168 1593,4210 1593,4315 1575,4333 1519,4333 ; 1462,7747 1474.01,7759.01 1551,7759.01 1593,7801.01 1593,7906.01 1575,7924.01 1519,7924.01 ; 1486.86,4387.14 1487,4387 ; 1486.86,7978.15 1487,7978.01 ; T5.3@1487.83,4461.83 T5.3@1487.83,4474.14 ; v1(1519.68,1224.63) 1520.47,1225.42 R28.1@1520.47,1295.03 ; v1(1548,1733) 1548,1789 ; C14.2@1552.5,1019.63 1581.26,1048.39 v1(1581.26,1084.63) ; v1(1729.68,1224.63) 1730.47,1225.42 R30.1@1730.47,1295.03 ; C92.2@1742.75,1019.63 1771.51,1048.39 v1(1771.51,1084.63) ; U2.2@1749,3482.87 1749,3518.76 1756.24,3526 v1(1756,3526) ; U15.2@1750.12,7073.8 1750.12,7116.12 v1(1760,7126) ; C52.2@1761.5,1930 v1(1810.67,1930) ; C77.2@1762.6,5519.2 v1(1811.77,5519.2) ; C51.2@1775,2000 v1(1824.17,2000) ; C64.2@1775.5,3660 1823,3660 v1(1824,3659) ; C76.2@1776.1,5594.2 v1(1825.28,5594.2) ; C90.2@1776.62,7250.94 1824.12,7250.94 v1(1825.12,7249.94) ; C63.2@1791,3738 v1(1847,3738) ; C89.2@1792.12,7328.94 v1(1848.12,7328.94) ; v1(1849,1696) 1849,1701.09 1849.46,1701.54 U5.4@1849.46,1646.72 ; U5.5@1849.46,1861.28 v1(1849.46,1910.46) ; U18.4@1850.56,5233.42 1850.56,5284.56 v1(1851,5285) ; U18.5@1850.56,5447.98 v1(1850.56,5497.16) ; v1(1939.68,1224.63) 1940.47,1225.42 R36.1@1940.47,1295.03 ; C16.2@1956.99,1019.63 1985.75,1048.39 v1(1985.75,1084.63) ; v1(2097,7065) 2097,6996.09 R119.1@2097.09,6996 ; v1(2125.86,1219.63) 2150.47,1244.24 R29.1@2150.47,1295.03 ; C93.2@2162.75,1014.63 C93.2@2162.75,1019.63 2191.51,1048.39 v1(2191.51,1084.63) ; C31.1@2776.3,934.02 v1(2826.8,934.02) ; v1(3672.61,485.23) 3673.11,485.73 R8.1@3673.11,536.73 ; R8.1@3674.11,535.23 3725.11,535.23 v1(3725.61,534.73) ; v1(4682.5,471.5) 4683,472 R17.1@4683,523.01 ; R17.1@4684,521.5 4735,521.5 v1(4735.5,521) ; v1(5063.11,1000) R15.1@5123.11,1000 v1(5123.11,1065) ; v1(5849.09,637) C20.2@5849.09,702 ; v1(5849.09,767) C20.2@5849.09,702 ; v1(5909.09,702) C20.2@5849.09,702
  Top Layer w25: v1(2079,3482) 2079,3413.09 R77.1@2083.09,3409
  Top Layer w30: v1(3816.15,2970.11) 3817.05,2971.01 C97.2@3817.05,3035 ; v1(3816.15,4770.11) 3817.05,4771.01 C98.2@3817.05,4835 ; v1(3816.15,6561.12) 3817.05,6562.02 C99.2@3817.05,6626.01 ; v1(3816.15,8361.12) 3817.05,8362.02 C100.2@3817.05,8426.01 ; v1(3817.94,3099.89) 3817.05,3098.99 C97.2@3817.05,3035 ; v1(3817.94,4899.89) 3817.05,4898.99 C98.2@3817.05,4835 ; v1(3817.94,6690.9) 3817.05,6690 C99.2@3817.05,6626.01 ; v1(3817.94,8490.9) 3817.05,8490 C100.2@3817.05,8426.01 ; v1(3939.15,3035.11) 3939.04,3035 C97.2@3817.05,3035 ; v1(3939.15,4835.11) 3939.04,4835 C98.2@3817.05,4835 ; v1(3939.15,6626.12) 3939.04,6626.01 C99.2@3817.05,6626.01 ; v1(3939.15,8426.12) 3939.04,8426.01 C100.2@3817.05,8426.01
  Bottom Layer w20: v1(1009.76,461.13) C34.2@1056.26,461.13 1094.76,499.63 U13.4@1132.08,499.63 1196.26,499.63 1212.87,516.25 C35.2@1212.87,564.63 v1(1166.26,564.63) ; R53.1@1385.62,2135.72 1385.62,2189.05 v1(1399,2202.43) ; R93.1@1385.62,5726.72 1385.62,5780.06 v1(1399,5793.43) ; R72.1@1460.62,3927.29 1460.62,3980.62 v1(1474,3994) ; R114.1@1460.62,7518.3 1460.62,7571.72 v1(1474.1,7585.2) ; v1(1804.26,303.63) 1804.26,257.14 R123.1@1805.76,255.63 ; v1(1997.75,302.13) R122.2@1997.75,255.63 R122.2@1999.26,254.13 ; v1(5123.11,1065) 5133.51,1054.6 D26.1@5181.76,1054.6
  other v1: 5113.11,308 5163.11,308 4031.11,313 4081.11,313 3022.11,321.73 3072.11,321.73 5113.11,359 5163.11,359 4031.11,364 4081.11,364 3022.11,372.73 3072.11,372.73 5113.11,410 5163.11,410 4031.11,415 4081.11,415 3022.11,423.73 3072.11,423.73 412.37,457.02 1369,563 1409,563 641.41,586.69 2783.8,645.02 2501.8,662.02 2502.8,758.02 412.37,780.9 219.89,1231.5 261.89,1231.5 5724,1723 5774,1723 5824,1723 5724,1773 5774,1773 5824,1773 1390.26,1803.2 5699,3504 5749,3504 5799,3504 5699,3554 5749,3554 5799,3554 1475,3624 1425,3629 5725,5305 5775,5305 5825,5305 5725,5355 5775,5355 5825,5355 1390.26,5394.21 366.76,6149.3 366.76,6214.3 335.76,6263.3 394.76,6263.3 5742,7013 5792,7013 5842,7013 5742,7063 5792,7063 5842,7063 1475,7215.01 1425,7220.01
  other v2: 414.11,511.38 449.54,511.38 431.83,535 414.11,558.62 449.54,558.62 4293.04,586.26 4409.18,586.26 3284.04,594.99 3400.18,594.99 4293.04,617.76 4409.18,617.76 3284.04,626.49 3400.18,626.49 4293.04,649.25 4409.18,649.25 3284.04,657.98 3400.18,657.98 4293.04,680.75 4409.18,680.75 3284.04,689.48 3400.18,689.48 4293.04,712.24 4409.18,712.24 3284.04,720.98 3400.18,720.98 4293.04,743.74 4409.18,743.74 2680.18,745.5 2727.42,745.5 3284.04,752.47 3400.18,752.47 2703.8,763.22 4293.04,775.24 4321.98,775.24 4351.11,775.24 4380.24,775.24 4409.18,775.24 2680.18,780.94 2727.42,780.94 3284.04,783.97 3312.98,783.97 3342.11,783.97 3371.24,783.97 3400.18,783.97 414.11,835.25 449.54,835.25 431.83,858.87 414.11,882.5 449.54,882.5
NetC1_1: C1.1 R140.2 R141.1 U3.2 | length 215.3
  Top Layer w15: R141.1@200.33,788.87 R140.2@200.33,855.88 ; R140.2@201.83,857.38 300.19,857.38 314.48,871.67 U3.2@344.23,871.67
NetC1_2: C1.2 C101.1 CLK_3V3.1 R139.2 R140.1 U3.1 | length 115.1
  Top Layer w20: CLK_3V3.1@77,838 77,872 130,925 ; CLK_3V3.1@92.37,813.9 CLK_3V3.1@92.37,820
NetC2_1: C2.1 F1.1 Q3.3 R61.2 R64.2 T5.8
NetC3_1: C3.1 F2.1 Q7.3 R42.2 R45.2 T4.8
NetC4_1: C4.1 C5.1 J4.2 U7.7 U7.13 U7.14 U7.15 U7.16 U7.17 U7.18 U7.22 U7.43
  other v1: 3323.02,313.73 3373.02,313.73 3323.02,364.73 3373.02,364.73 3323.02,415.73 3373.02,415.73
  other v2: 3268.11,530 3413.11,530 3342.11,532
NetC6_1: C6.1 R5.1 U7.26 U7.27 U7.28 U7.42
  other v2: 3450.57,686.61 3484.04,686.61 3450.57,720.07 3450.57,754.32 3484.04,754.32
NetC7_1: C7.1 R129.2 R130.1 U6.2 | length 215.3
  Top Layer w15: R130.1@200.33,465 R129.2@200.33,532.01 ; R129.2@201.83,533.5 300.19,533.5 314.48,547.8 U6.2@344.23,547.8
NetC7_2: C7.2 C8.1 CLK_1V8.1 R128.2 R129.1 U6.1 | length 131
  Top Layer w20: CLK_1V8.1@85,490.02 85,559.65 128.37,603.02
NetC9_1: C9.1 R127.1 U6.5 U6.8 | length 214
  Top Layer w15: U6.5@519.43,496.61 519.43,454.36 v1(520.26,453.53) v1@520.26,444.91
  Bottom Layer w15: v1(520.26,453.53) v1(520.26,615.53)
NetC10_2: C10.2 U6.6 | length 75
  Top Layer w15: U6.6@519.43,522.2 C10.2@594.38,522.2
NetC12_1: C12.1 C13.1 L9.2 U16.3 | length 86.9
  Top Layer w15: C13.1@370.89,1363.35 375.57,1368.04 U16.3@455.89,1368.04
NetC17_2: C17.2 C20.1 R11.1 R146.2 U9.26
NetC18_1: C18.1 C19.1 J5.2 U8.13 U8.14 U8.15 U8.16 U8.17 U8.18 U8.22 U8.43
  other v1: 4332.02,305 4382.02,305 4332.02,356 4382.02,356 4332.02,407 4382.02,407
  other v2: 4351.11,523.27 4278.11,525 4423.11,525
NetC23_1: C23.1 R10.1 U8.26 U8.27 U8.28 U8.42
  other v2: 4459.57,677.87 4493.04,677.87 4459.57,711.34 4459.57,745.59 4493.04,745.59
NetC24_1: C24.1 C25.1 C26.1 C27.1 L5.2 R21.1 U11.3 | length 45
  Top Layer w15: 1572.22,630.22 U11.3@1617.19,630.22
  other v1: 1459,676 1524,676
NetC28_1: C28.1 R20.2 R26.1 U10.2 | length 217.4
  Top Layer w15: U10.2@2691.01,675.62 2691.01,645.87 2705.3,631.58 C28.1@2705.3,598.22 R20.2@2705.3,533.22 2706.79,531.72 R26.1@2773.8,531.72
NetC30_1: C30.1 R18.1 U10.5 U10.8 | length 199
  Top Layer w15: U10.5@2742.19,850.82 v1(2782.6,850.82)
  Bottom Layer w15: v1(2624.11,851) 2624.29,850.82 v1(2782.6,850.82)
NetC31_2: C31.2 U10.6 | length 88
  Top Layer w15: C31.2@2715.8,938.52 2716.6,937.73 U10.6@2716.6,850.82
NetC35_1: C35.1 U13.5 | length 127.9
  Bottom Layer w15: C35.1@1275.86,564.63 1275.86,513.14 1289.37,499.63 U13.5@1346.65,499.63
NetC36_1: C36.1 C37.1 C38.1 C39.1 L8.2 R31.1 U12.3
  other v1: 379.76,6430.3 421.76,6430.3
NetC44_1: C44.1 Q5.2 T2.5
NetC44_2: C44.2 R46.1
NetC45_1: C45.1 Q6.2 T2.1
NetC45_2: C45.2 R47.1
NetC47_1: C47.1 R45.1 U4.1
NetC48_1: C48.1 R52.2 U4.9 | length 230.4
  Top Layer w10: C48.1@1231.07,2432.13 R52.2@1231.07,2367.13 1320.87,2367.13 1334.44,2353.56 U4.9@1334.44,2297.13
NetC49_1: C49.1 R54.2 U4.10 | length 140.2
  Top Layer w10: C49.1@1231.5,2295.43 1232.92,2294 v3(1286,2294) 1311.62,2294 U4.10@1314.76,2297.13
  Bottom Layer w10: R54.2@1231.5,2295.43 1232.92,2294 v3(1286,2294)
NetC50_1: C50.1 R55.1 | length 65.9
  Top Layer w10: R55.1@1246.5,1857 C50.1@1312.43,1857
NetC53_1: C53.1 R60.1 U5.2 | length 252.9
  Top Layer w10: C53.1@1624.46,1708.65 1730.35,1708.65 1749.46,1689.54 U5.2@1749.46,1646.72 R60.1@1749.46,1571.05 R60.1@1750.5,1570
NetC53_2: C53.2 R57.2 U5.1 | length 156.7
  Top Layer w10: R57.2@1547.5,1656 1557.84,1645.65 C53.2@1624.46,1645.65 1625.52,1646.72 U5.1@1699.46,1646.72
NetC56_1: C56.1 Q1.2 T1.5
NetC56_2: C56.2 R65.1
NetC57_1: C57.1 Q2.2 T1.1 | length 3.5
  Top Layer w20: C57.1@2568.5,4345 C57.1@2571,4347.5
NetC57_2: C57.2 R66.1
NetC59_1: C59.1 R64.1 U1.1
NetC60_1: C60.1 R71.2 U1.9 | length 229.4
  Top Layer w10: C60.1@1306.5,4224.27 R71.2@1306.5,4161.14 1393.86,4161.14 1409.44,4145.56 U1.9@1409.44,4088.71
NetC61_1: C61.1 R73.2 U1.10 | length 142.7
  Top Layer w10: C61.1@1306.5,4087 1307.5,4086 v3(1364,4086) 1387.05,4086 U1.10@1389.76,4088.71
  Bottom Layer w10: R73.2@1306.5,4087 1307.5,4086 v3(1364,4086)
NetC62_1: C62.1 R75.1 | length 67.4
  Top Layer w10: R75.1@1320.43,3680.94 1386.43,3680.94 C62.1@1387.43,3681.94
NetC65_1: C65.1 R79.1 U2.4 | length 233.3
  Top Layer w10: C65.1@1650,3546.5 1725.5,3546.5 1770.13,3591.13 U2.4@1786.4,3591.13 1829.64,3591.13 R79.1@1854.5,3616
NetC65_2: C65.2 R76.2 U2.1 | length 131.8
  Top Layer w10: R76.2@1581.5,3480 1585,3483.5 C65.2@1650,3483.5 1710.96,3483.5 U2.1@1711.6,3482.87
NetC66_1: C66.1 F5.1 Q15.3 R82.2 R85.2 T8.8
NetC69_1: C69.1 Q13.2 T7.5
NetC69_2: C69.2 R86.1
NetC70_1: C70.1 Q14.2 T7.1
NetC70_2: C70.2 R87.1
NetC72_1: C72.1 R85.1 U17.1
NetC73_1: C73.1 R92.2 U17.9 | length 230.4
  Top Layer w10: C73.1@1231.07,6023.13 R92.2@1231.07,5958.13 1320.87,5958.13 1334.44,5944.57 U17.9@1334.44,5888.14
NetC74_1: C74.1 R94.2 U17.10 | length 130.7
  Top Layer w10: C74.1@1231.5,5886.43 1232.5,5885.43 v3(1277,5885.43) 1312.05,5885.43 U17.10@1314.76,5888.14
  Bottom Layer w10: R94.2@1231.5,5886.43 1232.5,5885.43 v3(1277,5885.43)
NetC75_1: C75.1 R95.1 | length 65.9
  Top Layer w10: R95.1@1246.5,5448.01 C75.1@1312.43,5448.01
NetC78_1: C78.1 R100.1 U18.2 | length 252.9
  Top Layer w10: C78.1@1625.56,5295.35 1731.46,5295.35 1750.56,5276.24 U18.2@1750.56,5233.42 1750.56,5157.75 R100.1@1751.61,5156.7
NetC78_2: C78.2 R97.2 U18.1 | length 160
  Top Layer w10: R97.2@1546.55,5245.85 1560.05,5232.35 C78.2@1625.56,5232.35 1626.62,5233.42 U18.1@1700.56,5233.42
NetC79_1: C79.1 F4.1 Q11.3 R103.2 R106.2 T6.8
NetC82_1: C82.1 Q9.2 T3.5
NetC82_2: C82.2 R107.1
NetC83_1: C83.1 Q10.2 T3.1 | length 3.5
  Top Layer w20: C83.1@2568.5,7936.01 C83.1@2571,7938.5
NetC83_2: C83.2 R108.1
NetC85_1: C85.1 R106.1 U14.1
NetC86_1: C86.1 R113.2 U14.9 | length 226.6
  Top Layer w10: C86.1@1306.5,7815.27 R113.2@1306.5,7752.15 1389.16,7752.15 1409.44,7731.87 U14.9@1409.44,7679.72
NetC87_1: C87.1 R115.2 U14.10 | length 126.9
  Top Layer w10: C87.1@1306.5,7678.01 1307.5,7677.01 v3(1352,7677.01) U14.10@1387.05,7677.01
  Bottom Layer w10: R115.2@1306.5,7678.01 1307.5,7677.01 v3(1352,7677.01)
NetC88_1: C88.1 R117.1 | length 67.4
  Top Layer w10: R117.1@1320.43,7271.95 1386.43,7271.95 C88.1@1387.43,7272.95
NetC91_1: C91.1 R121.1 U15.4 | length 223
  Top Layer w10: C91.1@1651.12,7137.43 1727.43,7137.43 1772.07,7182.07 U15.4@1787.52,7182.07 1855.49,7182.07 R121.1@1855.62,7181.94
NetC91_2: C91.2 R118.2 U15.1 | length 132.8
  Top Layer w10: R118.2@1580.19,7074.46 C91.2@1651.12,7074.44 1712.08,7074.44 U15.1@1712.72,7073.8
NetC97_1: C97.1 T2.3 T4.7
NetC98_1: C98.1 T1.3 T5.7
NetC99_1: C99.1 T7.3 T8.7
NetC100_1: C100.1 T3.3 T6.7
NetC102_1: C102.1 R1.1 U3.5 U3.8 | length 190.8
  Top Layer w15: v1(519.43,785) U3.5@519.43,820.49
  Bottom Layer w15: v1(519.43,785) 519.43,939.2 520.11,939.89 v1(520,940)
NetC103_2: C103.2 U3.6 | length 76.4
  Top Layer w15: U3.6@519.43,846.08 594.38,846.08 C103.2@595.37,847.07
NetC105_1: C105.1 C106.1 L1.2 U16.6 U16.10 U16.13 | length 398.8
  Top Layer w15: U16.10@455.89,1188.91 456.3,1188.5 526.39,1188.5 577.48,1239.59 577.48,1240.09 ; U16.6@455.89,1291.27 529.62,1291.27 577.48,1243.41 577.48,1240.09 ; U16.13@688.17,1240.09 577.48,1240.09
NetC107_2: C107.2 Y1.4 | length 78.4
  Top Layer w10: Y1.4@626.61,1487.76 703.35,1487.76 C107.2@704.5,1486.61
NetC108_2: C108.2 Y1.2 | length 73.5
  Top Layer w10: Y1.2@453.39,1582.24 453.39,1651.5 C108.2@456.39,1654.5
NetC109_1: C109.1 C116.1 D6.1 Q7.1 R42.1 | length 451.6
  Top Layer w8: Q7.1@1347.92,2021.54 1347.92,1982.13 R42.1@1351.62,1978.43
  Top Layer w20: R42.1@1351.62,1978.43 1395.43,1978.43 v1(1396,1979)
  Bottom Layer w20: C116.1@1288.46,1906.5 C109.1@1380,1906.5 1476.5,1906.5 1491.01,1921.01 D6.1@1491.01,1977.01 ; v1(1396,1979) 1397.99,1977.01 D6.1@1491.01,1977.01 ; D6.1@1493,1977.01 D6.1@1491.01,1977.01
NetC110_1: C110.1 C121.1 D11.1 Q3.1 R61.1 | length 404.2
  Top Layer w8: Q3.1@1420.8,3811.38 1420.8,3771.97 R61.1@1424.5,3768.27
  Top Layer w20: R61.1@1424.5,3768.27 v1(1469.27,3768.27)
  Bottom Layer w20: C121.1@1335,3734.96 1338.46,3731.5 C110.1@1430,3731.5 1506.5,3731.5 D11.1@1543.27,3768.27 ; v1(1469.27,3768.27) D11.1@1543.27,3768.27 ; D11.1@1559.16,3768.27 D11.1@1543.27,3768.27
NetC111_1: C111.1 C126.1 D17.1 Q15.1 R82.1 | length 463
  Top Layer w8: Q15.1@1347.92,5612.54 1347.92,5573.13 R82.1@1351.62,5569.43
  Top Layer w20: R82.1@1351.62,5569.43 1395.43,5569.43 v1(1396,5570.01)
  Bottom Layer w20: C126.1@1284.57,5505.7 C111.1@1376.1,5505.7 1382.6,5499.2 1486.1,5499.2 1493,5506.1 D17.1@1493,5559.75 1493,5568.02 1397.99,5568.02 v1(1396,5570.01)
NetC112_1: C112.1 C131.1 D23.1 Q11.1 R103.1 | length 427.4
  Top Layer w8: Q11.1@1420.8,7402.38 1420.8,7362.97 R103.1@1424.5,7359.27
  Top Layer w20: R103.1@1424.5,7359.27 v1(1469.27,7359.27)
  Bottom Layer w20: C131.1@1339.57,7320.7 C112.1@1431.1,7320.7 1502.6,7320.7 D23.1@1541.17,7359.27 ; v1(1469.27,7359.27) D23.1@1541.17,7359.27 ; D23.1@1559.16,7359.27 D23.1@1541.17,7359.27 ; D23.1@1568,7368.11 1550.01,7368.11 D23.1@1541.17,7359.27
NetC113_1: C113.1 R152.1 R153.1
  other v1: 4405,2871 4455,2871
NetC113_2: C113.2 D3.1 T2.10
  other v1: 4518,2664 4518,2714
NetC115_1: C115.1 D5.1 T2.6
  other v1: 4518,1869.99 4518,1919.99
NetC115_2: C115.2 R154.2 R155.2
  other v1: 4405,1712.99 4455,1712.99
NetC118_1: C118.1 R156.1 R157.1
  other v1: 4405,4666.5 4455,4666.5
NetC118_2: C118.2 D2.3 T1.10
  other v1: 4518,4459.5 4518,4509.5
NetC120_1: C120.1 D10.3 T1.6
  other v1: 4518,3665.5 4518,3715.5
NetC120_2: C120.2 R158.2 R159.2
  other v1: 4405,3508.5 4455,3508.5
NetC123_1: C123.1 R160.1 R161.1
  other v1: 4405,6462.01 4455,6462.01
NetC123_2: C123.2 D14.1 T7.10
  other v1: 4518,6255.01 4518,6305.01
NetC125_1: C125.1 D16.1 T7.6
  other v1: 4518,5461 4518,5511
NetC125_2: C125.2 R162.2 R163.2
  other v1: 4405,5304 4455,5304
NetC128_1: C128.1 R164.1 R165.1
  other v1: 4405,8257.51 4455,8257.51
NetC128_2: C128.2 D20.3 T3.10
  other v1: 4518,8050.51 4518,8100.51
NetC130_1: C130.1 D22.3 T3.6
  other v1: 4518,7256.5 4518,7306.5
NetC130_2: C130.2 R166.2 R167.2
  other v1: 4405,7099.5 4455,7099.5
NetC133_1: C133.1 R12.2 | length 63
  Top Layer w12: R12.2@5274.5,981 C133.1@5274.5,1044
NetD2_1: D2.1 D10.1 L2.1
  other v1: 4984,4209.5 5034,4209.5 5084,4209.5 4984,4259.5 5034,4259.5 5084,4259.5
NetD3_3: D3.3 D5.3 L3.1
  other v1: 4984,2413.99 5034,2413.99 5084,2413.99 4984,2463.99 5034,2463.99 5084,2463.99
NetD4_1: D4.1 R43.1 R44.2 | length 161.4
  Top Layer w20: D4.1@1216.15,2511.88 1218.15,2513.88 R43.1@1293.85,2513.88 1293.85,2435.93 R44.2@1297.35,2432.43
NetD4_2: D4.2 R41.2 T4.1 | length 172.6
  Top Layer w20: D4.2@1216.15,2590.62 1289.02,2590.62 1289.65,2591.25 R41.2@1289.65,2593.88 ; T4.1@1266.32,2677.27 1266.32,2663.68 1297.35,2632.65 R41.2@1297.35,2593.88
NetD7_1: D7.1 R48.1 | length 75.6
  Top Layer w20: R48.1@1815.65,2178.54 1820.76,2173.42 D7.1@1889.15,2173.42
NetD7_2: D7.2 Q5.1 R49.2 | length 940.5
  Top Layer w20: R49.2@1815.65,2115.11 1843.95,2086.8 D7.2@1889.15,2086.8 ; D7.2@1889.28,2086.8 2490.46,2086.8 Q5.1@2670.15,1907.11
NetD8_1: D8.1 R51.1 | length 77.1
  Top Layer w20: R51.1@1815.65,2243.11 1824.34,2251.81 D8.1@1889.15,2251.81
NetD8_2: D8.2 Q6.1 R50.2 | length 888
  Top Layer w20: R50.2@1814.65,2309.11 1843.95,2338.42 D8.2@1889.15,2338.42 2283.46,2338.42 2470.15,2525.11 Q6.1@2470.15,2668.11
NetD9_1: D9.1 R62.1 R63.2 | length 153.2
  Top Layer w15: R62.1@1370.37,4307.77 R62.1@1371,4307.14
  Top Layer w20: D9.1@1301,4307.77 R62.1@1370.37,4307.77 ; R62.1@1371,4307.14 1371,4229.19 R63.2@1374.5,4225.68
NetD9_2: D9.2 R2.2 T5.1 | length 173.2
  Top Layer w20: D9.2@1301,4386.51 1301.63,4387.14 R2.2@1374.5,4387.14 1374.5,4429.5 1342.17,4461.83 T5.1@1342.17,4473.16
NetD12_1: D12.1 R67.1 | length 77.6
  Top Layer w20: R67.1@1814.5,3974 1819.19,3969.31 D12.1@1890.13,3969.31
NetD12_2: D12.2 Q1.1 R68.2 | length 941.8
  Top Layer w20: R68.2@1814.5,3909 1840.8,3882.69 D12.2@1890.13,3882.69 2491.31,3882.69 Q1.1@2671,3703
NetD13_1: D13.1 R70.1 | length 79.1
  Top Layer w20: R70.1@1814.5,4039 1823.19,4047.69 D13.1@1890,4047.69
NetD13_2: D13.2 Q2.1 R69.2 | length 889.4
  Top Layer w20: R69.2@1814.5,4104 1844.8,4134.31 D13.2@1890,4134.31 2284.31,4134.31 2471,4321 Q2.1@2471,4464
NetD14_3: D14.3 D16.3 L7.1
  other v1: 4984,6005 5034,6005 5084,6005 4984,6055 5034,6055 5084,6055
NetD15_1: D15.1 R83.1 R84.2 | length 153.2
  Top Layer w20: D15.1@1223.85,6105.52 1224.48,6104.89 R83.1@1293.85,6104.89 1293.85,6026.94 R84.2@1297.35,6023.43
NetD15_2: D15.2 R81.2 T8.1 | length 170
  Top Layer w20: D15.2@1223.85,6184.26 1224.48,6184.89 R81.2@1297.35,6184.89 1297.35,6223.95 1266.32,6254.99 T8.1@1266.32,6268.28
NetD18_1: D18.1 R88.1 | length 75.6
  Top Layer w20: R88.1@1815.65,5769.54 1820.76,5764.43 D18.1@1889.15,5764.43
NetD18_2: D18.2 Q13.1 R89.2 | length 940.5
  Top Layer w20: R89.2@1815.65,5706.12 1843.95,5677.81 D18.2@1889.15,5677.81 ; D18.2@1889.28,5677.81 2490.46,5677.81 Q13.1@2670.15,5498.12
NetD19_1: D19.1 R91.1 | length 77.1
  Top Layer w20: R91.1@1815.65,5834.12 1824.34,5842.81 D19.1@1889.15,5842.81
NetD19_2: D19.2 Q14.1 R90.2 | length 888
  Top Layer w20: R90.2@1814.65,5900.12 1843.95,5929.43 D19.2@1889.15,5929.43 2283.46,5929.43 2470.15,6116.12 Q14.1@2470.15,6259.12
NetD20_1: D20.1 D22.1 L6.1
  other v1: 4986,7728.99 5036,7728.99 5086,7728.99 4986,7778.99 5036,7778.99 5086,7778.99
NetD21_1: D21.1 R104.1 R105.2 | length 153.2
  Top Layer w20: D21.1@1301,7898.78 1370.37,7898.78 R104.1@1371,7898.15 1371,7820.19 R105.2@1374.5,7816.69
NetD21_2: D21.2 R102.2 T6.1 | length 173.2
  Top Layer w20: D21.2@1301,7977.52 1301.63,7978.15 R102.2@1374.5,7978.15 1374.5,8019.8 1342.17,8052.14 T6.1@1342.17,8064.16
NetD24_1: D24.1 R109.1 | length 77.6
  Top Layer w20: R109.1@1814.5,7565.01 1819.19,7560.31 D24.1@1890.13,7560.31
NetD24_2: D24.2 Q9.1 R110.2 | length 941.8
  Top Layer w20: R110.2@1814.5,7500.01 1840.8,7473.7 D24.2@1890.13,7473.7 2491.31,7473.7 Q9.1@2671,7294.01
NetD25_1: D25.1 R112.1 | length 79.1
  Top Layer w20: R112.1@1814.5,7630.01 1823.19,7638.7 D25.1@1890,7638.7
NetD25_2: D25.2 Q10.1 R111.2 | length 889.4
  Top Layer w20: R111.2@1814.5,7695.01 1844.8,7725.32 D25.2@1890,7725.32 2284.31,7725.32 2471,7912.01 Q10.1@2471,8055.01
NetF2_2: F2.2 R3.2
NetF3_2: F3.2 R4.2
NetF4_2: F4.2 R101.2
NetF5_2: F5.2 R80.2
NetQ4_1: Q4.1 R76.1 R78.2 | length 154
  Top Layer w10: Q4.1@1367,3480.89 1449.64,3480.89 R78.2@1452.2,3483.45 1515.06,3483.45 R76.1@1518.5,3480
NetQ4_2: Q4.2 Q4.4 R75.2 U1.3 | length 671.7
  Top Layer w10: v3(1209,3681) v3(1209,3681) R75.2@1257.43,3680.94 1257.43,3540.62 Q4.4@1256.76,3539.94 Q4.2@1359.13,3539.94 ; v3(1364,3863) 1400,3863 1429.13,3892.13 U1.3@1429.13,3927.29
  Bottom Layer w10: v3(1209,3681) 1209,3744 1328,3863 v3(1364,3863)
NetQ8_1: Q8.1 R57.1 R58.2 | length 151.3
  Top Layer w10: Q8.1@1332.26,1655.09 1334.82,1657.65 R58.2@1417.46,1657.65 R57.1@1482.46,1657.65
NetQ8_2: Q8.2 Q8.4 R55.2 U4.3 | length 686.1
  Top Layer w10: v3(1145,1857) R55.2@1183.5,1857 1183.5,1808.5 1222.02,1769.98 Q8.4@1222.02,1714.15 Q8.2@1324.39,1714.15 ; v3(1289,2071.43) 1325,2071.43 1354.13,2100.55 U4.3@1354.13,2135.72
  Bottom Layer w10: v3(1145,1857) 1145,1927.43 v3(1289,2071.43)
NetQ12_1: Q12.1 R118.1 R120.2 | length 147.6
  Top Layer w10: Q12.1@1367,7071.9 R120.2@1449.64,7071.9 ; R120.2@1452.2,7074.46 R118.1@1517.2,7074.46
NetQ12_2: Q12.2 Q12.4 R117.2 U14.3 | length 675.2
  Top Layer w10: v3@1209.06,7271.95 R117.2@1257.43,7271.95 1256.76,7271.28 Q12.4@1256.76,7130.95 Q12.2@1359.13,7130.95 ; v3(1364,7454.01) 1400,7454.01 1429.13,7483.13 U14.3@1429.13,7518.3
  Bottom Layer w10: v3(1209,7272.01) 1209,7341.1 1321.91,7454.01 v3(1364,7454.01)
NetQ16_1: Q16.1 R97.1 R98.2 | length 149.9
  Top Layer w10: Q16.1@1334.82,5248.66 R98.2@1417.46,5248.66 1480.75,5248.66 R97.1@1483.56,5245.85
NetQ16_2: Q16.2 Q16.4 R95.2 U17.3 | length 686.1
  Top Layer w10: v3(1145,5448.01) R95.2@1183.5,5448.01 1183.5,5399.5 1222.02,5360.98 Q16.4@1222.02,5305.16 Q16.2@1324.39,5305.16 ; v3@1289,5662.43 v3(1289.31,5662.43) 1325,5662.43 1354.13,5691.56 U17.3@1354.13,5726.72
  Bottom Layer w10: v3(1145,5448.01) 1145,5518.43 v3@1289,5662.43
NetR7_2: R7.2 U7.9 | length 95
  Top Layer w15: R7.2@3067.11,545.73 3100.62,579.24 U7.9@3148.21,579.24
NetR9_1: R9.1 U11.13 | length 117.3
  Top Layer w10: U11.13@1849.48,655.82 1927.67,655.82 R9.1@1955.36,628.13
NetR12_1: R12.1 U9.31 | length 79.2
  Top Layer w12: R12.1@5337.5,981 5353.98,964.52 U9.31@5353.98,908.58
NetR14_2: R14.2 U8.9 | length 95
  Top Layer w15: R14.2@4076.11,537 4109.62,570.51 U8.9@4157.21,570.51
NetR15_2: R15.2 U9.36 | length 102.3
  Top Layer w15: U9.36@5176.81,908.58 5176.81,938.7 5203.11,965 R15.2@5203.11,1000
NetR16_1: R16.1 U9.30 | length 114.8
  Top Layer w15: U9.30@5389.41,908.58 5389.41,946.3 5409.57,966.46 R16.1@5409.57,1015
NetR22_2: R22.2 U11.11 VCON-B1.1 | length 376.5
  Top Layer w10: U11.11@1849.48,604.63 1804.37,604.63 1791.33,617.67 1791.33,700.84 R22.2@1849,758.5 1996.5,758.5 VCON-B1.1@1997,758
NetR23_2: R23.2 U11.10 VCON-D1.1 | length 433.5
  Top Layer w10: R23.2@1773.33,758.14 1773.33,589.67 1783.96,579.04 U11.10@1849.48,579.04 ; R23.2@1783,758.5 1751.3,790.2 1751.3,878.3 VCON-D1.1@1787.76,914.76
NetR24_2: R24.2 U11.5 VCON-C1.1 | length 568.8
  Top Layer w10: VCON-C1.1@1577,919 1640,919 1687.3,871.7 1687.3,790.2 R24.2@1719,758.5 ; U11.5@1617.19,579.04 1733.22,579.04 1744.37,590.19 1744.37,727.11 R24.2@1713.33,758.14
NetR25_2: R25.2 U11.4 VCON-A1.1 | length 610.7
  Top Layer w10: VCON-A1.1@1377,919 1424,919 1584.86,758.14 R25.2@1653.33,758.14 1714.37,697.11 1714.37,618.61 1700.39,604.63 U11.4@1617.19,604.63
NetR27_2: R27.2 U13.6 VREF_5V.1 | length 257.6
  Bottom Layer w20: U13.6@1346.65,449.63 R27.2@1454.65,449.63 1454.65,312.24 VREF_5V.1@1463.26,303.63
